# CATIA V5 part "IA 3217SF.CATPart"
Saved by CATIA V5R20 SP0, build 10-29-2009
Part number: IA 3217SF
Revision: ANY
Definition: UNKNOWN
Nomenclature: IA 3217SF
Source: Unknown
Bounding box of the stored display mesh (mm): x -1.6 to 1.6, y -8.75 to 8.2, z -1.6 to 1.6
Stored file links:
  C:\Users\Utente\Desktop\IO LAVORO\3D X SITO CF\CUMSA\3D files FA\FA 0632SF\IA 3217SF.CATPart

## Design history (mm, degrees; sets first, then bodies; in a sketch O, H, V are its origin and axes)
Body1 "Cortar-Extruir2" (main body)
  Solid1: solid without history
